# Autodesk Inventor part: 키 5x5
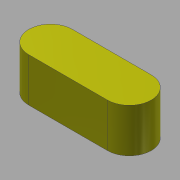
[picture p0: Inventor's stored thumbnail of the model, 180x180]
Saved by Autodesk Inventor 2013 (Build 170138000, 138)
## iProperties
Created: 2016-04
Part Number: 키 5x5
Document SubType Name: Modeling
Designer: mdu
Density: 7.86 g/cm^3
Mass: 2.54015 g
Surface Area: 2.9781 cm^2
Volume: 0.323175 cm^3
Material: 강철, 연강
Author: mdu
Revision Number: 1
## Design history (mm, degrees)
sketch "스케치1"
  geometry: L1 (-4.5, -2.5)-(4.5, -2.5); L2 (4.5, 2.5)-(-4.5, 2.5); A1 r 2.5 centre (4.5, 0) between (4.5, -2.5) and (4.5, 2.5); A2 r 2.5 centre (-4.5, 0) between (-4.5, 2.5) and (-4.5, -2.5); 2 further points
  constraints: 4 end point, 4 point on circle, 4 tangent, 2 centre point, 1 horizontal, 1 horizontal alignment, 1 midpoint, 1 parallel, 1 vertical alignment
  dimensions: "d0" = 5 distance between parallel lines of L1 L2; "d1" = 14 dimension on A1 A2
extrude "돌출1" new body sketch "스케치1" stored distance "d2" = 5; taper "d3" = 0 deg
node "솔리드1"
